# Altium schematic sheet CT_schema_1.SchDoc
size 659 x 258 mm
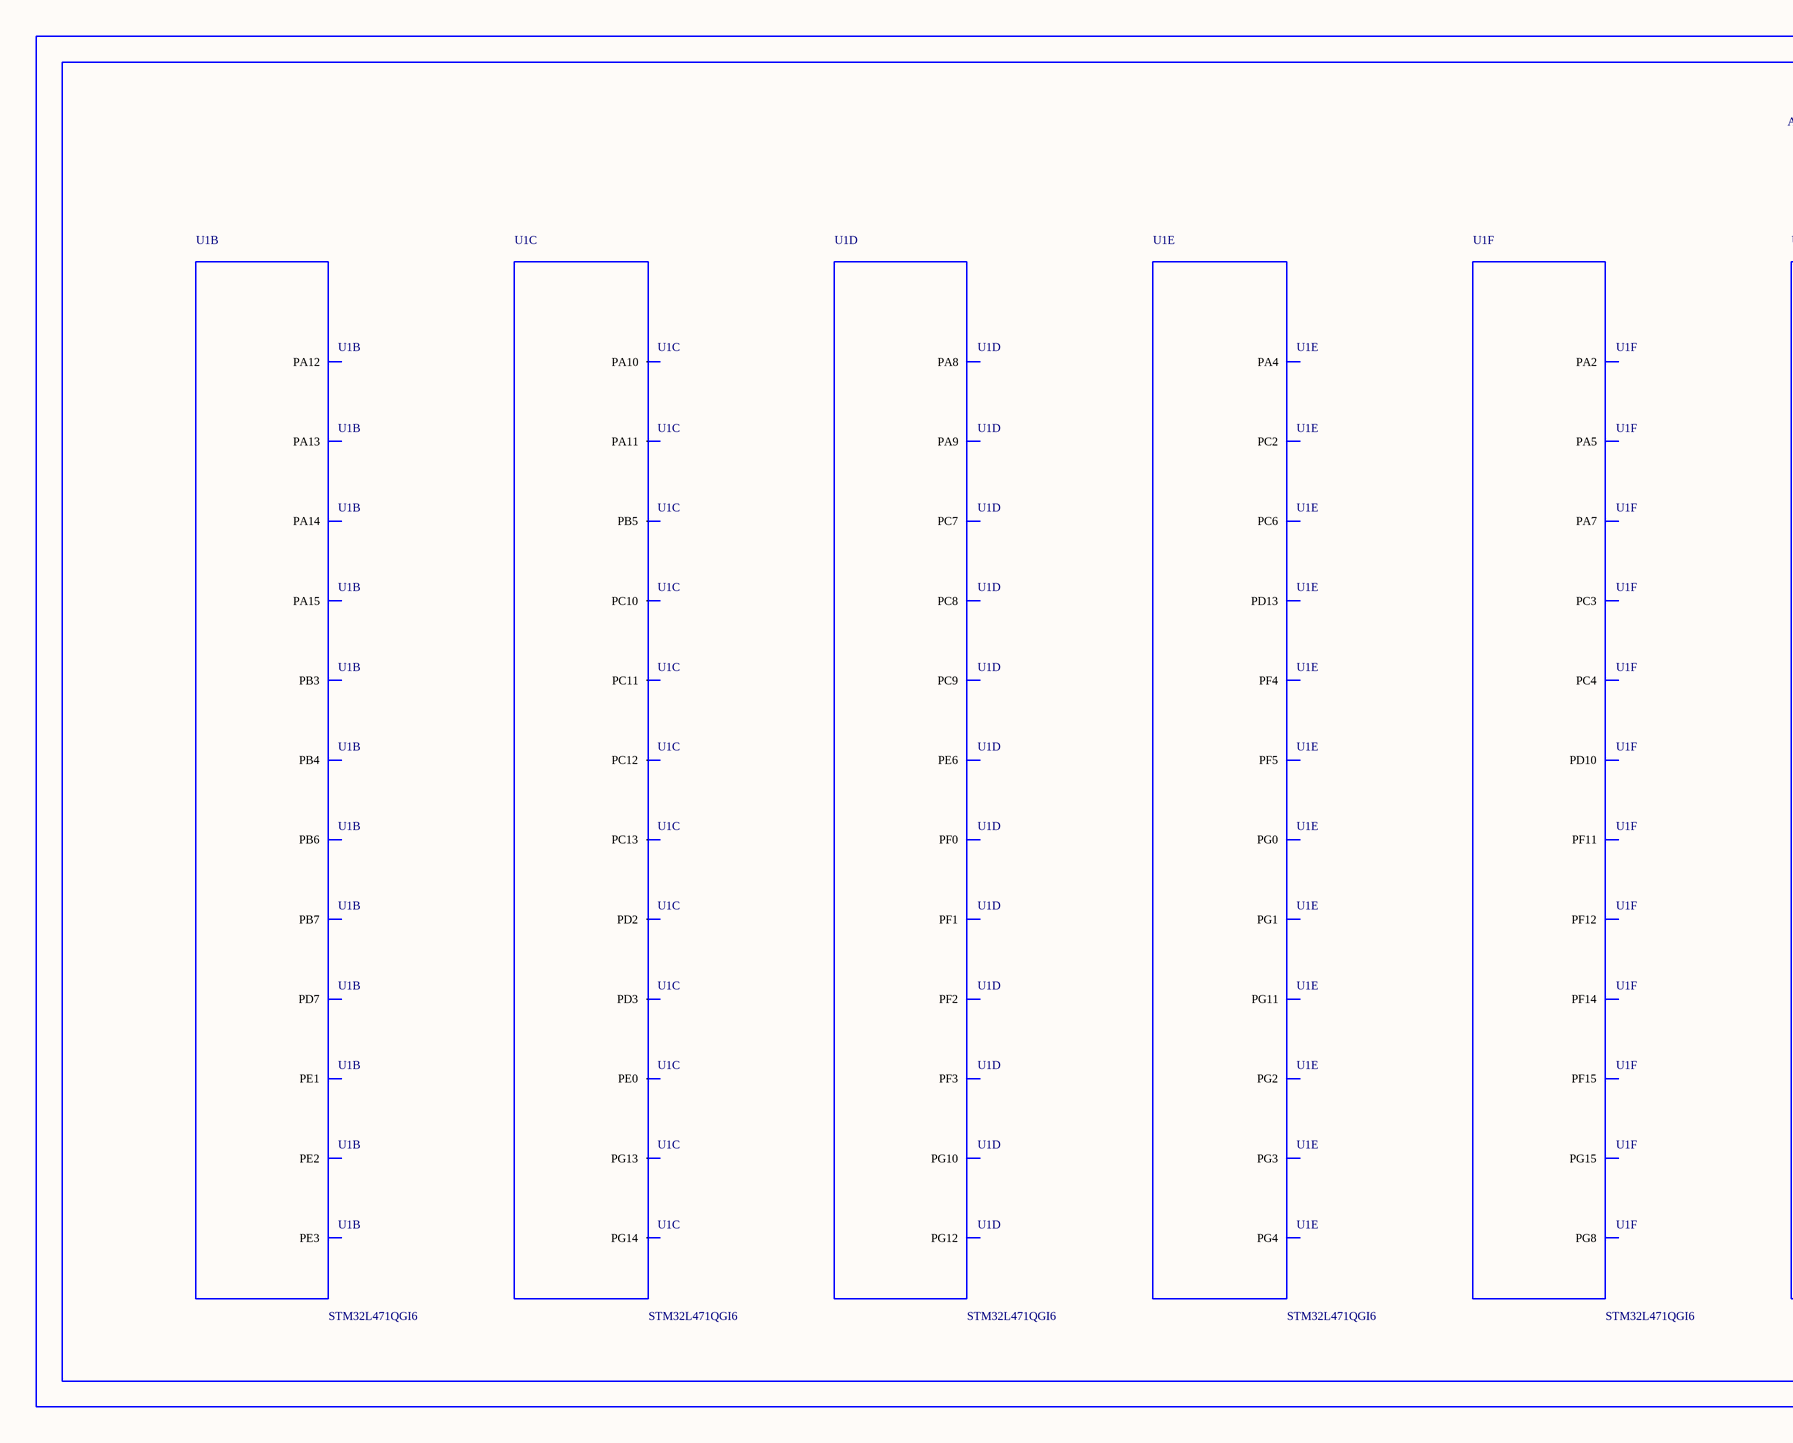
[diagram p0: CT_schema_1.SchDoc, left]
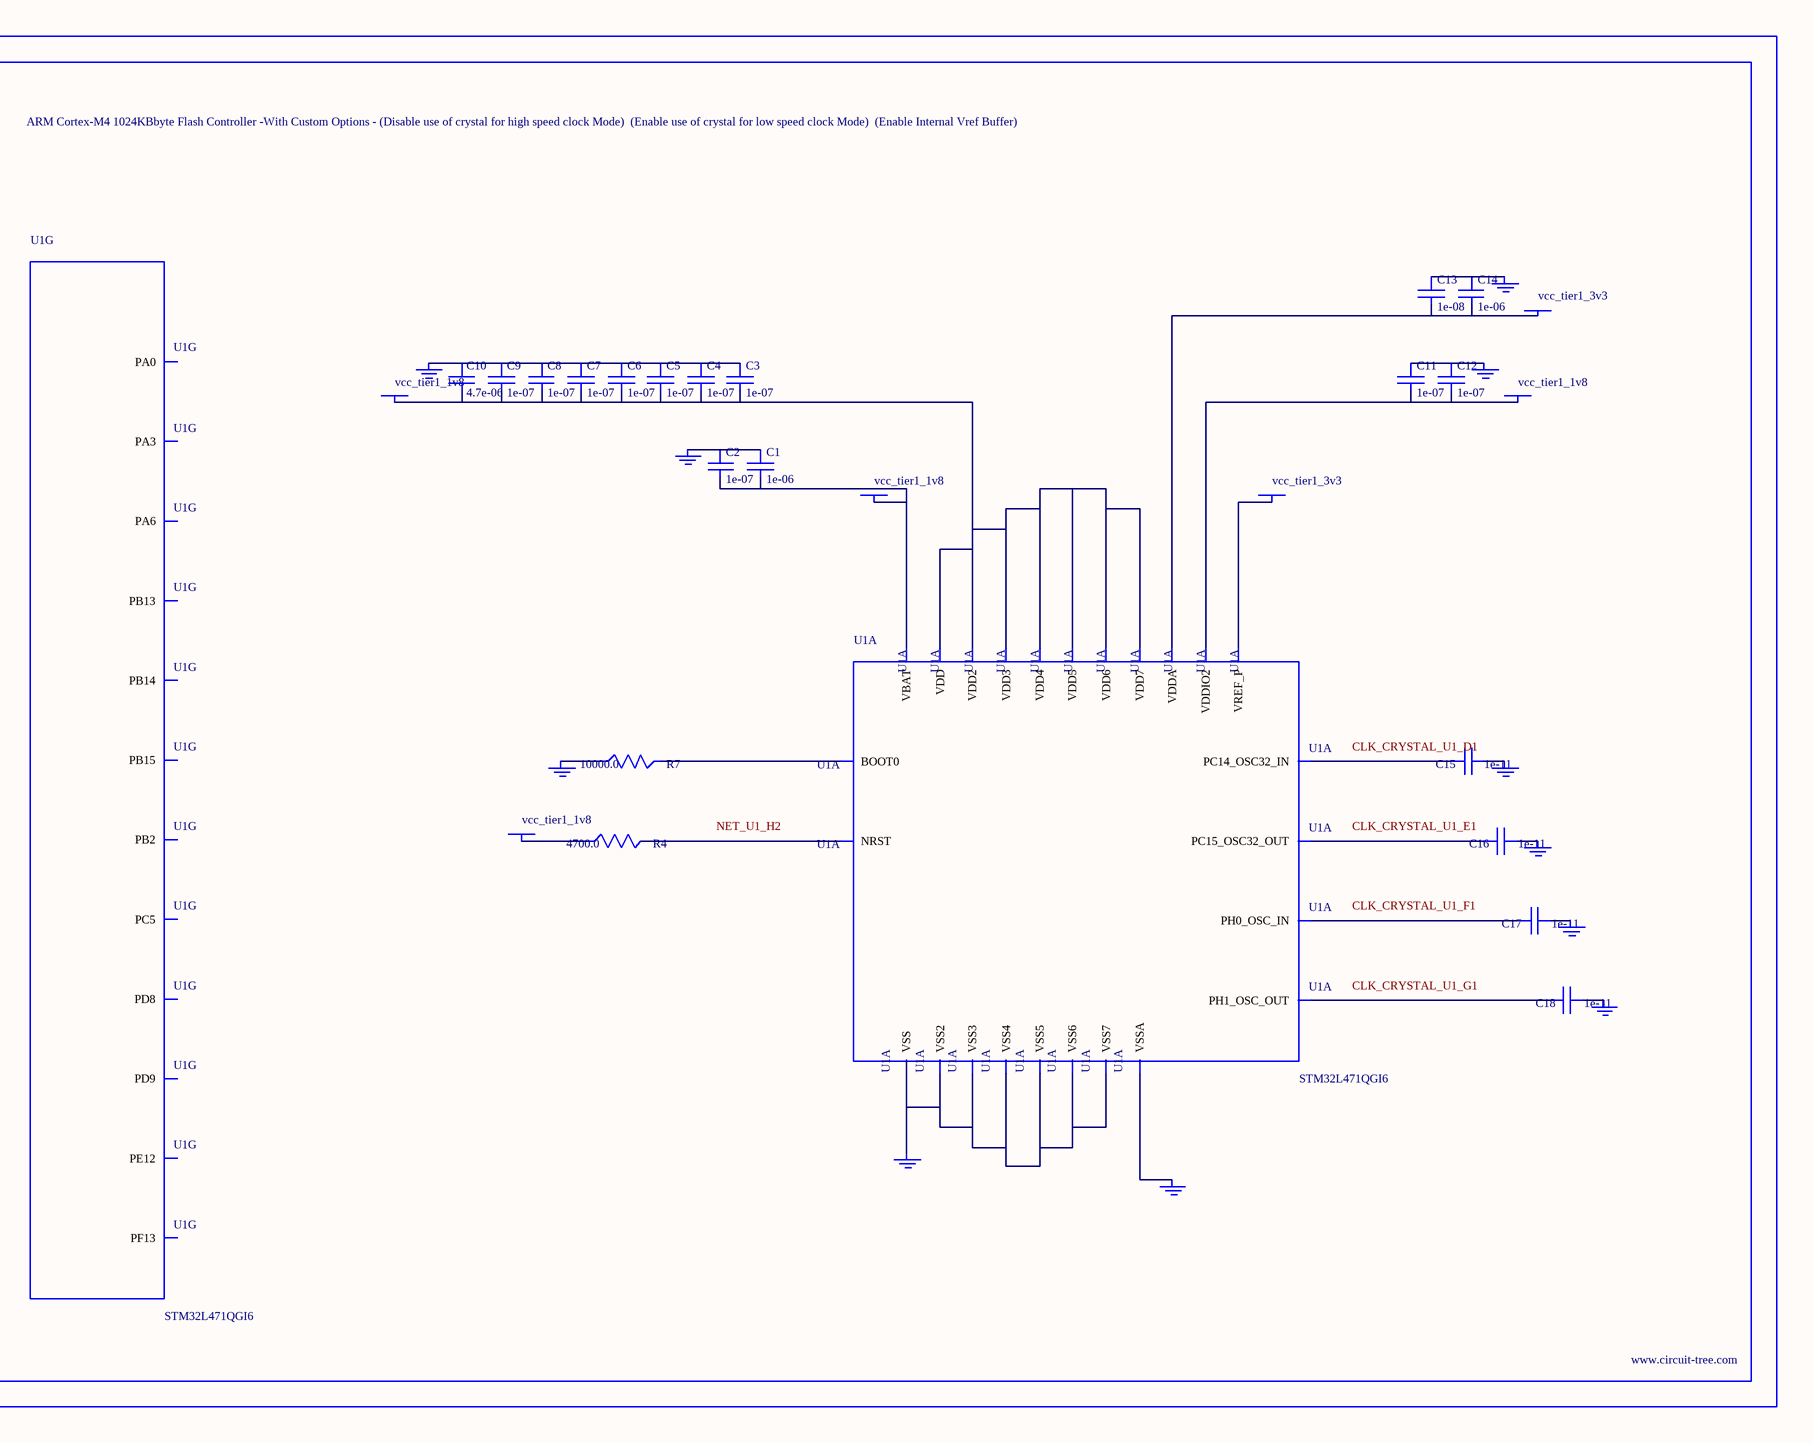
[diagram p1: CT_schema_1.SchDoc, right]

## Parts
BORDER0  (no value)
C1  1e-06  [C0603]
C2  1e-07  [C0603]
C3  1e-07  [C0603]
C4  1e-07  [C0603]
C5  1e-07  [C0603]
C6  1e-07  [C0603]
C7  1e-07  [C0603]
C8  1e-07  [C0603]
C9  1e-07  [C0603]
C10  4.7e-06  [C0603]
C11  1e-07  [C0603]
C12  1e-07  [C0603]
C13  1e-08  [C0603]
C14  1e-06  [C0603]
C15  1e-11  [C0402]
C16  1e-11  [C0402]
C17  1e-11  [C0402]
C18  1e-11  [C0402]
GND_INSTANCE_0_0  (no value)
GND_INSTANCE_0_1  (no value)
GND_INSTANCE_0_2  (no value)
GND_INSTANCE_0_3  (no value)
GND_INSTANCE_0_4  (no value)
GND_INSTANCE_0_5  (no value)
GND_INSTANCE_0_6  (no value)
GND_INSTANCE_0_7  (no value)
GND_INSTANCE_0_8  (no value)
GND_INSTANCE_0_9  (no value)
GND_INSTANCE_0_10  (no value)
POWER_INSTANCE_0_0  vcc_tier1_1v8
POWER_INSTANCE_0_1  vcc_tier1_1v8
POWER_INSTANCE_0_2  vcc_tier1_1v8
POWER_INSTANCE_0_3  vcc_tier1_3v3
POWER_INSTANCE_0_4  vcc_tier1_3v3
POWER_INSTANCE_0_5  vcc_tier1_1v8
R4  4700.0  [R0603]
R7  10000.0  [R0603]
U1  STM32L471QGI6  [UFBGA132]  (parts A,B,C,D,E,F,G of 12)

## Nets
NetC1_1: C1.1 C2.1 GND_INSTANCE_0_0.0(GND)
NetC1_2: C1.2 C2.2 POWER_INSTANCE_0_0.0(PWR) U1.E2(VBAT)
NetC3_1: C3.1 C4.1 C5.1 C6.1 C7.1 C8.1 C9.1 C10.1 GND_INSTANCE_0_1.0(GND)
NetC3_2: C3.2 C4.2 C5.2 C6.2 C7.2 C8.2 C9.2 C10.2 POWER_INSTANCE_0_1.0(PWR) U1.C4(VDD2) U1.C11(VDD) U1.G2(VDD5) U1.G6(VDD6) U1.G11(VDD3) U1.G12(VDD4) U1.H3(VDD7)
NetC11_1: C11.1 C12.1 GND_INSTANCE_0_2.0(GND)
NetC11_2: C11.2 C12.2 POWER_INSTANCE_0_2.0(PWR) U1.G7(VDDIO2)
NetC13_1: C13.1 C14.1 GND_INSTANCE_0_4.0(GND)
NetC13_2: C13.2 C14.2 POWER_INSTANCE_0_3.0(PWR) U1.M1(VDDA)
NetC15_1: C15.1 GND_INSTANCE_0_5.0(GND)
NetC15_2: C15.2 U1.D1(PC14_OSC32_IN)
NetC16_1: C16.1 GND_INSTANCE_0_6.0(GND)
NetC16_2: C16.2 U1.E1(PC15_OSC32_OUT)
NetC17_1: C17.1 GND_INSTANCE_0_7.0(GND)
NetC17_2: C17.2 U1.F1(PH0_OSC_IN)
NetC18_1: C18.1 GND_INSTANCE_0_8.0(GND)
NetC18_2: C18.2 U1.G1(PH1_OSC_OUT)
NetGND_INSTANCE_0_3_0: GND_INSTANCE_0_3.0(GND) R7.1
NetGND_INSTANCE_0_9_0: GND_INSTANCE_0_9.0(GND) U1.J1(VSSA)
NetGND_INSTANCE_0_10_0: GND_INSTANCE_0_10.0(GND) U1.D3(VSS) U1.E3(VSS2) U1.F2(VSS5) U1.F6(VSS6) U1.F7(VSS7) U1.F11(VSS3) U1.F12(VSS4)
NetPOWER_INSTANCE_0_4_0: POWER_INSTANCE_0_4.0(PWR) U1.L1(VREF_P)
NetPOWER_INSTANCE_0_5_0: POWER_INSTANCE_0_5.0(PWR) R4.1
NetR4_2: R4.2 U1.H2(NRST)
NetR7_2: R7.2 U1.A4(BOOT0)

Not connected (* = marked no-connect by the designer): U1 A1(PE3) A2(PE1) A5(PD7) A7(PB4) A8(PB3) A9(PA15) A10(PA14) A11(PA13) A12(PA12) B2(PE2) B4(PB7) B5(PB6) B8(PD3) B10(PC12) B11(PC10) B12(PA11) C1(PC13) C3(PE0) C5(PB5) C6(PG14) C7(PG13) C8(PD2) C10(PC11) C12(PA10) D2(PE6) D4(PF2) D5(PF1) D6(PF0) D7(PG12) D8(PG10) D10(PA9) D11(PA8) D12(PC9) E4(PF3) E10(PC8) E11(PC7) E12(PC6) F3(PF4) F4(PF5) F9(PG3) F10(PG4) G3(PG11) G9(PG1) G10(PG2) H9(PG0) H12(PD13) J3(PC2) J4(PA4) J5(PA7) J6(PG8) J7(PF12) J8(PF14) J9(PF15) J12(PD10) K1(PG15) K2(PC3) K3(PA2) K4(PA5) K5(PC4) K6(PF11) K7(PF13) K8(PD9) K9(PD8) K10(PB15) K11(PB14) K12(PB13) L2(PA0) L3(PA3) L4(PA6) L5(PC5) L6(PB2) L9(PE12)

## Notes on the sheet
- Labels drawn without touching a wire or pin: CLK_CRYSTAL_U1_D1, CLK_CRYSTAL_U1_E1, CLK_CRYSTAL_U1_F1, CLK_CRYSTAL_U1_G1, NET_U1_H2

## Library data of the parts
BORDER0 = BORDER_PAGE0
C1 C14 = C0603C105K3RACTU
C2-C9 C11 C12 = 06035C104K4Z2A
C10 = GRM188R6YA475KE15D
C13 = 06035C103K4Z2A
C15-C18 = C0402C100K3GACTU
GND_INSTANCE_0_0-GND_INSTANCE_0_10 = GND
POWER_INSTANCE_0_0-POWER_INSTANCE_0_5 = PWR
R4 = RC0603JR-074K7L
R7 = RC0603JR-0710KL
